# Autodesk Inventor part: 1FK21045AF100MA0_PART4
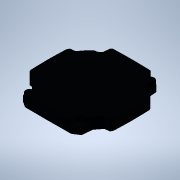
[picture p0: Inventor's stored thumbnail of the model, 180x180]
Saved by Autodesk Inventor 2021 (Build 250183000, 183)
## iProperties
Created: 2025-04
Part Number: 1FK21045AF100MA0_PART4
Material: Generic
Catalog Web Link: www.3dfindit.com
Description: -Servo synchronous motor
Document SubType Name: Modeling
Designer: psAdmin
Mass: 55.5405 g
Surface Area: 149.572 cm^2
Volume: 55.5405 cm^3
Density: 1 g/cm^3
Appearance: PSOLRGB-38-46-56
Category: PARTsolutions
Title: 1FK21045AF100MA0_PART4
Author: Cadenas PARTsolutions
Comments: Servo synchronous motor
Sending System: PARTsolutions
Preprocessor: ST-DEVELOPER v19.3
PSOL_IDENT_0: {$CADENAS_DATA/23d-libs/siemens_ag/_cat_/52/6b/1fk21045af100ma0.prj},213 {VTYP=3D},{NB=1FK21045AF100
PSOL_IDENT_1: MA0_PART4},{LINA=1FK21045AF100MA0_PART4},{NN=1FK21045AF100MA0_PART4},{NOPRJ=TRUE},{DATE=19.08.2025 1
PSOL_IDENT_2: 4:00:38},{GEOMDATE=30.07.2025 02:01:45},{VERSION=},{LINEID=10},{WBVAR=},{WBNUMERIC=}  {NB=1FK21045AF
PSOL_IDENT_3: 100MA0_PART4},{LINA=1FK21045AF100MA0_PART4},{KT=DUMMY},{PREVIEW=../../../_pool_/cb/72/p_d211_xx_0043
PSOL_IDENT_4: 4j.png},{DESCSHORT=SIMOTICS S-1FK2 HD, SINAMICS S210 3AC 400V-480V, 2.4 Nm, 3000 rpm},{DESCLONG=SIMO
PSOL_IDENT_5: TICS S-1FK2 HD servo motor M0=2.4 Nm; PN = 0.75 kW at nN=3000 rpm (380-480 V); PN = 0.375 kW at nN=1
PSOL_IDENT_6: 500 rpm (200-240 V); with holding brake; degree of protection IP64; cylindrical shaft D19x40mm; abso
PSOL_IDENT_7: lute encoder 22-bit + 12-bit multiturn (encoder AM22DQC); with OCC interface; plug size M17, rotatab
PSOL_IDENT_8: le; SIMOTICS S-1FK2 servomotorfor a wide range of uses in industrial environments. SIMOTICS S‑1FK2 s
PSOL_IDENT_9: ervomotors are compact synchronous motors with a high dynamic performance that set themselves apart
PSOL_IDENT_10: as a result of their high power density, degree of protection and overload capability. The motors ar
PSOL_IDENT_11: e available in two variants: as High Dynamic variant (highest dynamic performance as a result of the
PSOL_IDENT_12: low intrinsic moment of inertia for applications demanding a high dynamic performance with low move
PSOL_IDENT_13: d masses) - and as Compact variant (precise and stable closed-loop control for medium up to large mo
PSOL_IDENT_14: ved masses as a result of a medium intrinsic moment of inertia). SIMOTICSS‑1FK2 servomotors fully ex
PSOL_IDENT_15: ploit their strengths in a system with the SINAMICSS210 frequency converter and simple connection us
PSOL_IDENT_16: ing the one cable connection (OCC). Advantages include the short control and positioning times, fast
PSOL_IDENT_17: and precise correction of disturbing quantities as well as stable control with a high dynamic perfo
PSOL_IDENT_18: rmance. The servo motors can be configured to address a wide range of requirements. For example with
PSOL_IDENT_19: and without holding brake, IP64 or IP65 degree of protection, singleturn or multiturn absolute enco
PSOL_IDENT_20: ders - to name just a few. Further, the servomotors are available in different shaft heights extendi
PSOL_IDENT_21: ng from 20 to 100. A shaft sealing ring is available to achieve an IP65 degree of protection and for
PSOL_IDENT_22: subsequent mounting at the motor or as spare part. SIMOTICS - the optimum motor for each and every
PSOL_IDENT_23: motion control application.},{INTNO=804766906411},{SUPPLIERALTNO=1FK2104-5AF10-0MA0},{MANUID=1FK2104
PSOL_IDENT_24: 5AF100MA0},{MANUNAME=Siemens},{MANUTYPEDESC=Synchronous motor 1FK2-HD 2.4 NM},{AAU732=SIMOTICS},{AAO
PSOL_IDENT_25: 057=S-1FK2},{AAU734=SIMOTICS S-1FK2 HD servo motor M0=2.4 Nm; PN = 0.75 kW at nN=3000 rpm (380-480 V
PSOL_IDENT_26: ); PN = 0.375 kW at nN=1500 rpm (200-240 V); with holding brake; degree of protection IP64; cylindri
PSOL_IDENT_27: cal shaft D19x40mm; absolute encoder 22-bit + 12-bit multiturn (encoder AM22DQC); with OCC interface
PSOL_IDENT_28: ; plug size M17, rotatable;},{AAW338=Synchronous motor 1FK2-HD 2.4 NM},{AAO742=SIMOTICS},{AAO663=404
PSOL_IDENT_29: 2948693070},{NOCUPEROU=1},{PRICEQUANTITY=1},{QUANTITYMIN=1},{QUANTITYINT=1},{CTN=85015100},{COO=DE},
PSOL_IDENT_30: {AAO676=1FK2104-5AF10-0MA0},{AAO677=Siemens AG},{ORDERUNIT=C62},{CONTENTUNIT=C62}
NB: 1FK21045AF100MA0_PART4
NT: Servo synchronous motor
NBSYN: $MANUID._PART4
LINA: 1FK21045AF100MA0_PART4
CATALOG: SIEMENS
PREVIEW: ../../../_pool_/cb/72/p_d211_xx_00434j.png
DESCSHORT: SIMOTICS S-1FK2 HD, SINAMICS S210 3AC 400V-480V, 2.4 Nm, 3000 rpm
DESCLONG: SIMOTICS S-1FK2 HD servo motor M0=2.4 Nm; PN = 0.75 kW at nN=3000 rpm (380-480 V); PN = 0.375 kW at nN=1500 rpm (200-240 V); with holding brake; degree of prote
INTNO: 804766906411
SUPPLIERALTNO: 1FK2104-5AF10-0MA0
MANUID: 1FK21045AF100MA0
MANUNAME: Siemens
MANUTYPEDESC: Synchronous motor 1FK2-HD 2.4 NM
AAU732: SIMOTICS
AAO057: S-1FK2
AAU734: SIMOTICS S-1FK2 HD servo motor M0=2.4 Nm; PN = 0.75 kW at nN=3000 rpm (380-480 V); PN = 0.375 kW at nN=1500 rpm (200-240 V); with holding brake; degree of prote
AAW338: Synchronous motor 1FK2-HD 2.4 NM
AAO742: SIMOTICS
AAO663: 4042948693070.0
NOCUPEROU: 1
PRICEQUANTITY: 1
QUANTITYMIN: 1
QUANTITYINT: 1
CTN: 85015100
COO: DE
ARTICLENO: 1FK21045AF100MA0_PART4
BOMINFO: 1FK21045AF100MA0_PART4
CREATOR: CADENAS GmbH
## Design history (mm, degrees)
feature "2025_04_17_15_34_52_0223"
body "Solid1"
